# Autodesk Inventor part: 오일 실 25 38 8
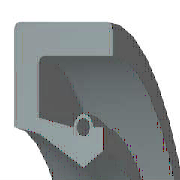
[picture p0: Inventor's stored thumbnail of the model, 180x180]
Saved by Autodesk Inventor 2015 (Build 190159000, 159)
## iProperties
IsCustomPart: 1
Created: 2012-02
Part Number: 오일 실 25 38 8
Material: 고무
Description: 오일-실
Document SubType Name: Modeling
Standard: KS B 2804
Designer: mduedu
Standards Organization: KS
Language: ko-KR
Size Designation: S - 25 38 8
Categories: <MemberInstance><Categories><Category DisplayName="샤프트 부품" InternalName="7f7aeb1f-a693-4053-b835-cee3144e0d98" Mnemonic="SHFT"><Category DisplayName="실링" Intern
Density: 0.93 g/cm^3
Appearance: 고무 - 검은색 - 버전 1.1
Author: mduedu
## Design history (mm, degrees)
revolve "본체" stored, may be unused: angle "d17" = 90 deg
revolve "스프링1" stored, may be unused: angle "d18" = 90 deg
body "Solid1"
sketch "스케치1"
  geometry: L1 (0, 19)-(8, 19); L2 (8, 19)-(8, 17.75); L3 (8, 17.75)-(1.75, 17.75); L4 (0, 19)-(0, 14.6); L5 (0, 14.6)-(1.75, 14.25); L6 (1.75, 14.25)-(4.9, 12.5); L7 (4.9, 12.5)-(0, 12.5); L8 (6.3, 13.375)-(6.3, 14.6); L9 (0, 0)-(9.586, 0) reference; L10 (4.9, 12.5)-(6.3, 13.375); L11 (0, 18)-(0, -3) reference; L12 (-1.917, 0)-(11.503, 0) reference; L13 (4.2, 14.6)-(1.75, 15.09); L14 (1.75, 15.09)-(1.75, 17.75); L15 (6.3, 14.6)-(5.6, 14.6); C1 r 0.455 at (4.9, 14.6); A1 r 0.7 centre (4.9, 14.6) between (5.6, 14.6) and (4.2, 14.6)
  constraints: 26 end point, 5 horizontal alignment, 4 perpendicular, 2 centre point, 2 collinear, 2 horizontal, 2 parallel, 2 point on circle, 2 point on line, 2 vertical alignment, 1 coincident
  dimensions: "d0" = 38 diameter of L1 L9 (= SD2); "d1" = 26.75 diameter of L8.start L9 (= ABDM); "d2" = 1.25 distance of L1.end L2.end (computed from SD); "d3" = 0.91 diameter of C1 (= SPDI); "d4" = 1.4 diameter of A1 (= SPDA); "d5" = 25 diameter of L6.end L9 (= NND); "d6" = 28.5 diameter of L5.end L9 (= TKDM); "d7" = 29.2 diameter of L4.end L9 (= HLDM); "d8" = 4.9 distance from line of C1.centre L4 (= SPDST); "d9" = 6.3 distance between parallel lines of L8 L4 (= SDI); "d10" = 8 distance between parallel lines of L2 L4 (= SWDT); "d12" = 1.75 distance between parallel lines of L14 L4 (= SD)
fillet "모깎기1" dims "d11" = 0.5 (= RR)
other parameters: "SD2" = 38 [user parameter; used in 1 equation term], "SWDT" = 8 [user parameter; used in 1 equation term], "RR" = 0.5 [user parameter; used in 1 equation term], "SD" = 1.75 [user parameter; used in 2 equation terms], "NND" = 25 [user parameter; used in 1 equation term], "SPDA" = 1.4 [user parameter; used in 1 equation term], "SPDI" = 0.91 [user parameter; used in 1 equation term], "TKDM" = 28.5 [user parameter; used in 1 equation term], "HLDM" = 29.2 [user parameter; used in 1 equation term], "ABDM" = 26.75 [user parameter; used in 1 equation term], "SDI" = 6.3 [user parameter; used in 1 equation term], "SPDST" = 4.9 [user parameter; used in 1 equation term], "d13" = 0, "d14" = 0, "d15" = 0, "LAB" = 0.35 [user parameter]
